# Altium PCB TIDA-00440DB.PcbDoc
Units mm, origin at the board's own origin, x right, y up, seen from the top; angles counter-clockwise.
Board outline 75 x 52 mm, 2 copper layers (Top Layer, Bottom Layer), stack 1.575 mm thick; 55 components, 30 nets, 111 pads, 12 vias.
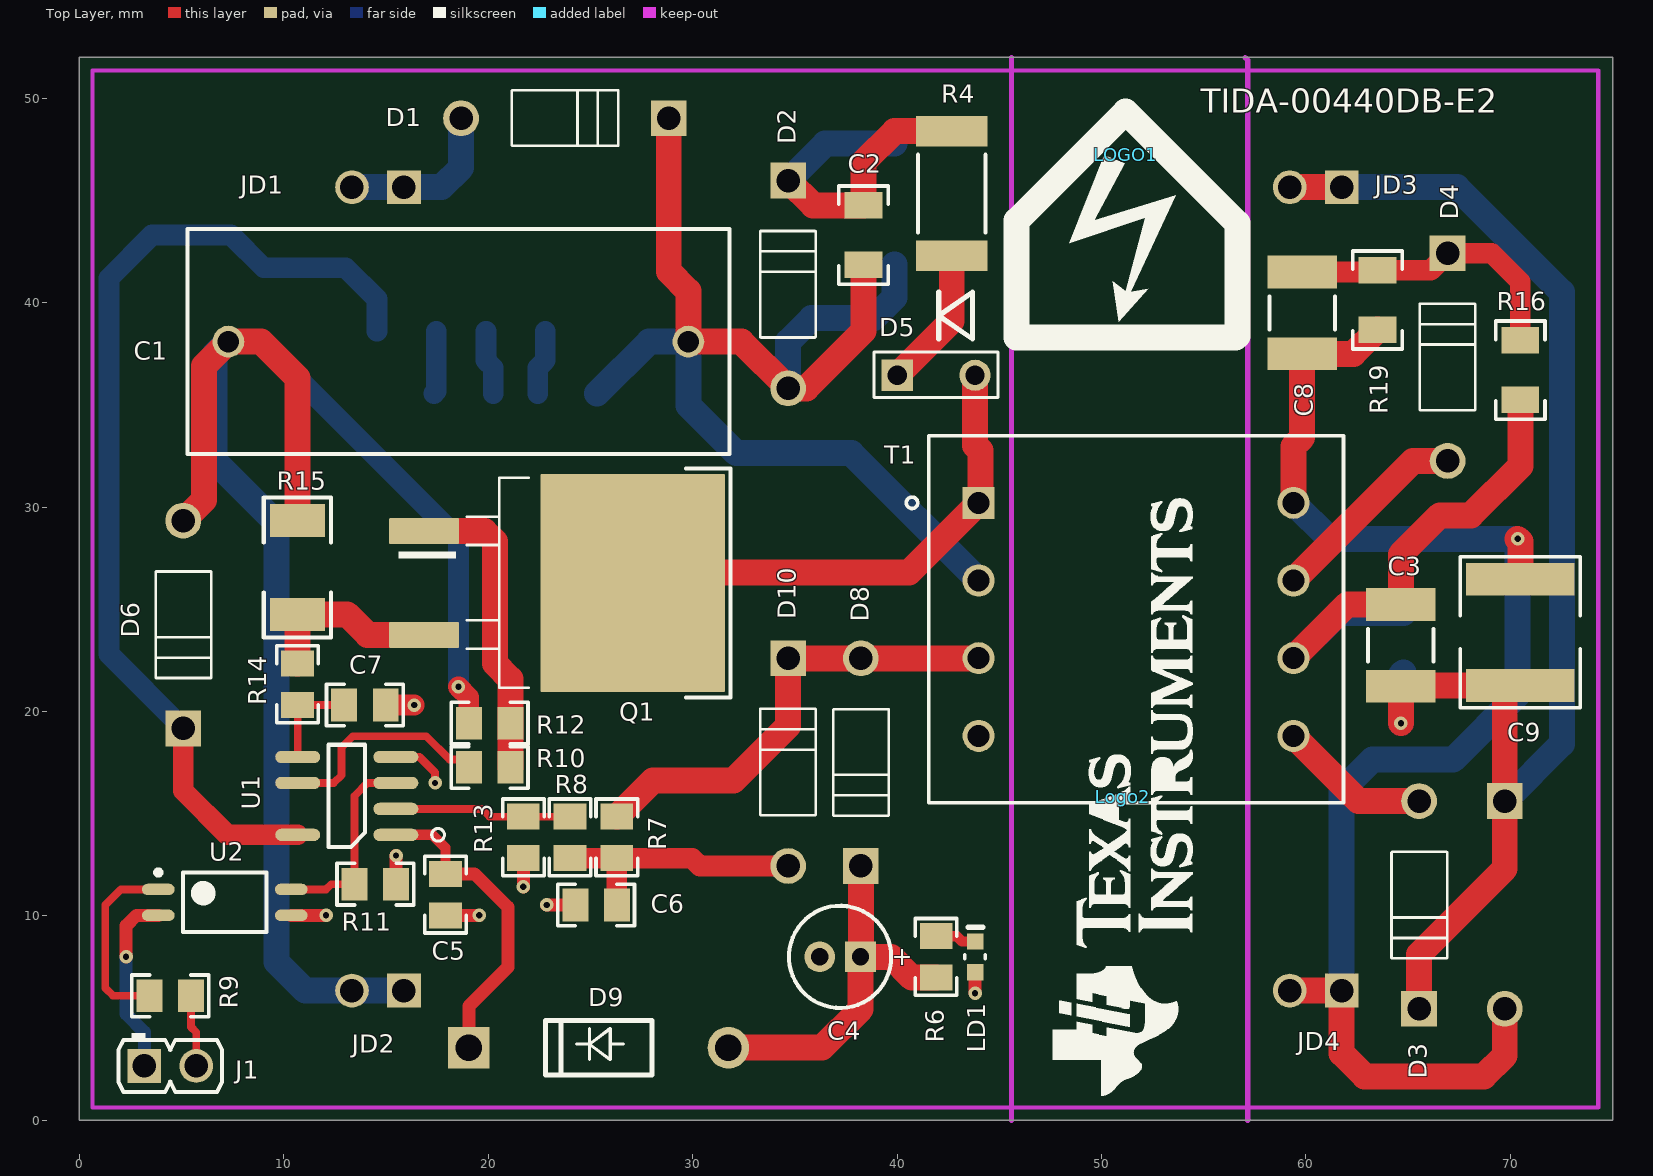
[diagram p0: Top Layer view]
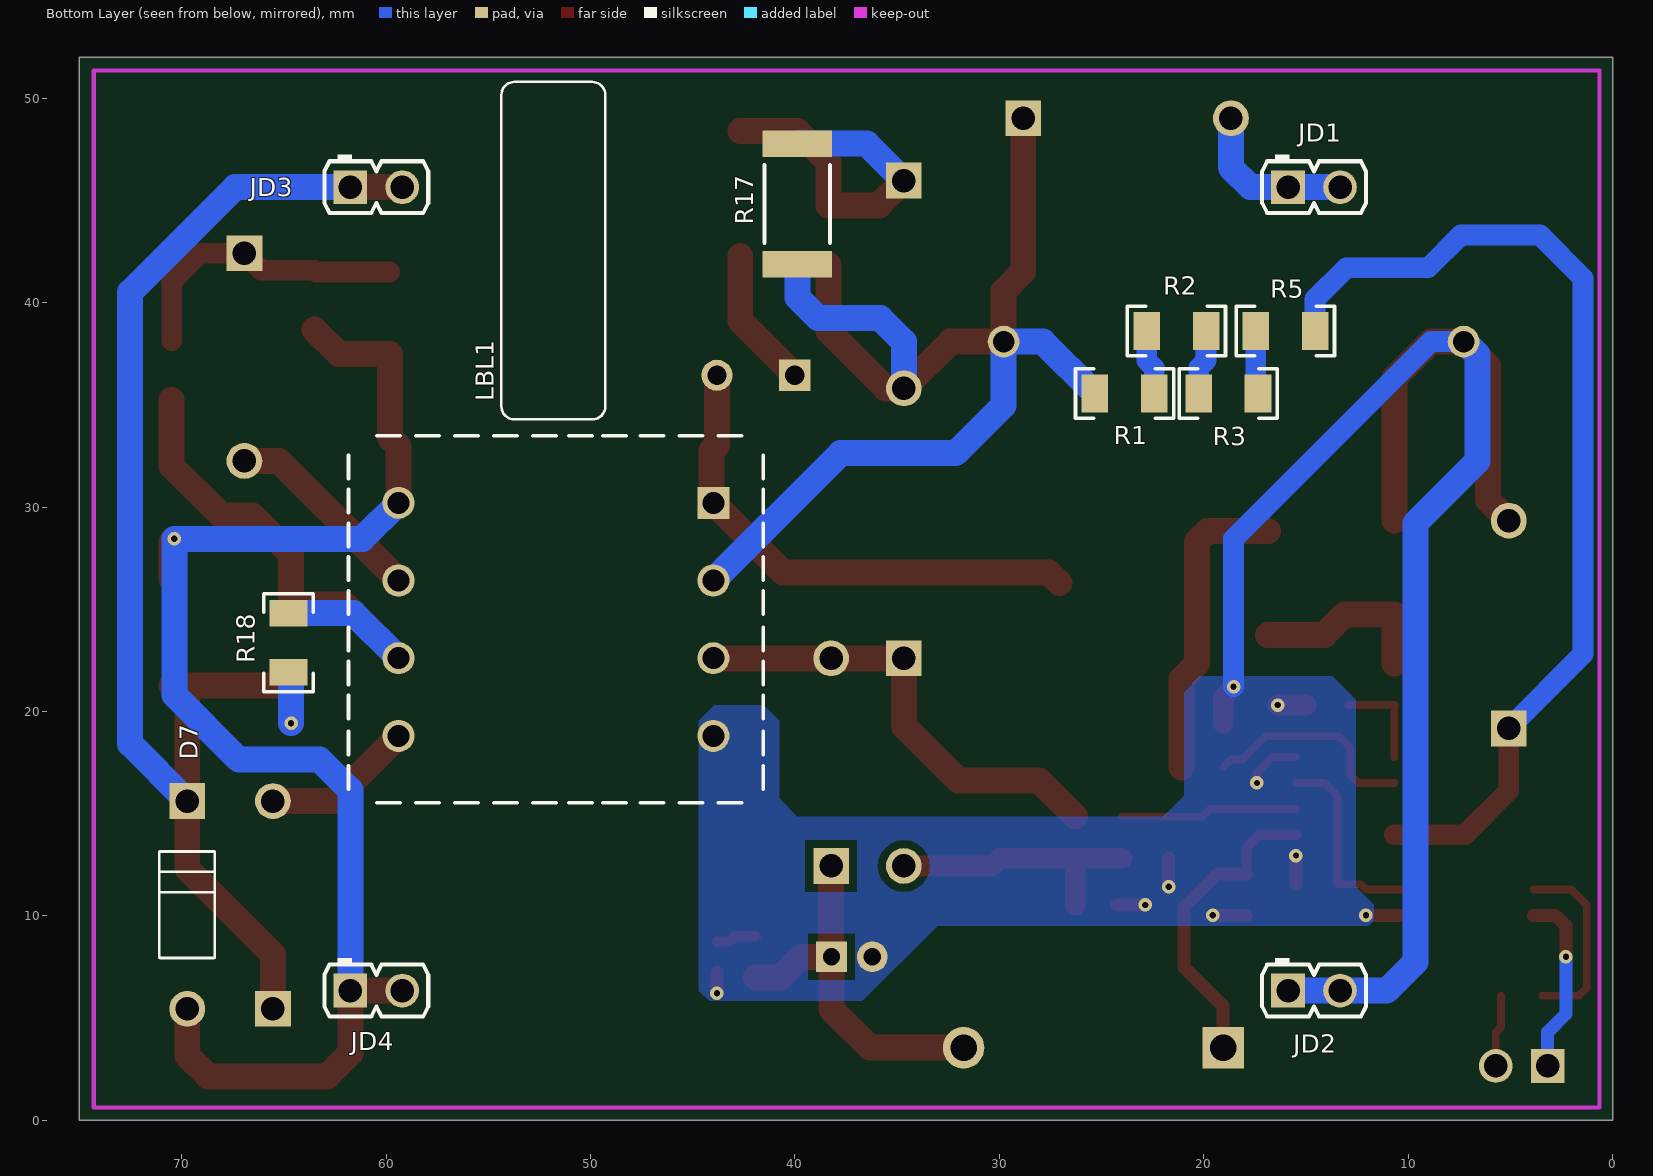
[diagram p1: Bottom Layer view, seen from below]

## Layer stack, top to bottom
Top Layer: signal copper 0.0356
Dielectric: core 1.5037, FR-4, Dk 4.8
Bottom Layer: signal copper 0.0356

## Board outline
0,0 0,52 75,52 75,0

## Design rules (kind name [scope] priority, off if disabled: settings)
AcuteAngle [All] p1: minimum=4.50000000000000E+0001 checktracksonly=FALSE
AssemblyTestPointUsage [All] p1: valid=2
Clearance "Poly_ All" [InPolygon] p1: gap=0.381
Clearance "Less Than 9 mils from PAD to PAD" [(InPadClass('Less than 9 Mil Clearance')) vs (InPadClass('All Pads'))] p2: gap=0.178
Clearance "SMT Pin Via" [IsVia vs IsSMTPin] p3: gap=0.203
Clearance "Via to Via" [IsVia vs IsVia] p4: gap=0.203
Clearance Poly_Poly [InPolygon vs InPolygon] p5: gap=0.381
Clearance [All] p6: gap=0.203
ComponentClearance ComponentClearance_Shunt [InComponentClass('Header') vs InComponentClass('Shunt')] p1: gap=0 collisioncheckmode=3 verticalgap=0 showdistances=FALSE
ComponentClearance ComponentClearance_Logo [InComponentClass('Logo')] p2: gap=1.27 collisioncheckmode=3 verticalgap=0.254 showdistances=FALSE
ComponentClearance ComponentClearance_ScrewToNut [(HasFootprint('NY PMS 440 0025 PH')) vs (HasFootprint('Keystone_1902C'))] p3: gap=0.127 collisioncheckmode=3 verticalgap=0.254 showdistances=FALSE
ComponentClearance ComponentClearance_MountingHoles [InComponentClass('Mounting Holes')] p4: gap=6.35 collisioncheckmode=3 verticalgap=2540 showdistances=FALSE
ComponentClearance ComponentClearance_SmallPassives [HasFootprint('0201*') or HasFootprint('0402*') or HasFootprint('0508') or HasFootprint('0603*') or HasFootprint('0612') or HasFootprint('0805*') or HasFootprint('0815*') or HasFootprint('0830*') or HasFootprint('1206*') or HasFootprint('1210*') or HasFootprint('1808*') or HasFootprint('1812*') or HasFootprint('1825*') or HasFootprint('2010*') or HasFootprint('2220*') or HasFootprint('2225*') or HasFootprint('2512*') or HasFootprint('2728*') or HasFootprint('3518*') vs HasFootprint('0201*') or HasFootprint('0402*') or HasFootprint('0508') or HasFootprint('0603*') or HasFootprint('0612') or HasFootprint('0805*') or HasFootprint('0815*') or HasFootprint('0830*') or HasFootprint('1206*') or HasFootprint('1210*') or HasFootprint('1808*') or HasFootprint('1812*') or HasFootprint('1825*') or HasFootprint('2010*') or HasFootprint('2220*') or HasFootprint('2225*') or HasFootprint('2512*') or HasFootprint('2728*') or HasFootprint('3518*')] p5: gap=0.508 collisioncheckmode=3 verticalgap=0.254 showdistances=FALSE
ComponentClearance ComponentClearance_THtoSMT [IsThruComponent vs IsSMTComponent] p6: gap=2.54 collisioncheckmode=3 verticalgap=0.762 showdistances=FALSE
ComponentClearance ComponentClearance_THtoTH [IsThruComponent vs IsThruComponent] p7: gap=3 collisioncheckmode=3 verticalgap=0.762 showdistances=FALSE
ComponentClearance [All] p8: gap=1.016 collisioncheckmode=3 verticalgap=0.254 showdistances=FALSE
DiffPairsRouting [All] p1: maxlimit=2.54 minlimit=0.254 mostfreqgap=0.254 maxuncoupledlength=25.4
FabricationTestPointUsage TestPointUsage [All] p1: valid=2 allowmultiple=FALSE
FabricationTestpoint Testpoint [All] p1: side=3 testpointundercomponent=TRUE minsize=1.016 maxsize=2.54 preferedsize=1.524 minholesize=0 maxholesize=1.016 preferedholesize=0.813 testpointgrid=0.025 allowsidetop=TRUE allowsidebottom=TRUE usegrid=TRUE gridtolerance=0
FanoutControl Fanout_LCC [IsLCC] p1: bgadir=Out bgaviamode=Centered fanoutstyle=Auto fanoutdirection=Alternating viagrid=0.025 // Fanout_LCC (Default Rule)
FanoutControl Fanout_BGA [IsBGA] p2: bgadir=Out bgaviamode=Centered fanoutstyle=Auto fanoutdirection=Alternating viagrid=0.025 // Fanout_BGA (Default Rule)
FanoutControl Fanout_Default [All] p4: bgadir=Out bgaviamode=Centered fanoutstyle=Auto fanoutdirection=Alternating viagrid=0.025 // Fanout_Default (Default Rule)
FanoutControl Fanout_Small [(CompPinCount < 5)] p5: bgadir=Out bgaviamode=Centered fanoutstyle=Auto fanoutdirection=OutThenIn viagrid=0.025 // Fanout_Small (Default Rule)
HoleSize [All] p1: absolutevalues=TRUE maxlimit=6.375 minlimit=0.203 maxpercent=80.000 minpercent=20.000
MinimumAnnularRing MinimumAnnularRing_ThermalPadVias [IsVia and InAnyComponent] p1: minimumring=0.15
MinimumAnnularRing [All] p2: minimumring=0.15
MinimumSolderMaskSliver MinimumSolderMaskSliver_Logo [InComponentClass('Logo') vs InComponentClass('Logo')] p1: minsoldermaskwidth=0.018
MinimumSolderMaskSliver [All] p2: minsoldermaskwidth=0.1
PlaneConnect [All] p1: planeconnectstyle=Relief reliefexpansion=0.254 reliefentries=4 reliefconductorwidth=0.254 reliefairgap=0.254
PolygonConnect [All] p1: connectstyle=Direct reliefconductorwidth=0.254 reliefentries=4 polygonreliefangle="90 Angle" airgapwidth=0.254
RoutingVias [All] p1: holewidth=0.305 width=0.66 viastyle="Through Hole" minholewidth=0.305 minwidth=0.66 maxholewidth=0.508 maxwidth=1.016
SMDToCorner [All] p1: distance=30000
SilkToSilkClearance [All] p1: silktosilkclearance=0.127
SilkscreenOverComponentPads [All] p1: minsilkscreentomaskgap=0.127
SolderMaskExpansion [All] p1: expansion=0.064
Width [All] p1: maxlimit=2.54 minlimit=0.203 preferedwidth=0.203 checkconnectedcopper=TRUE
14 further rules are at their usual default settings.

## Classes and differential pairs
component class Label: LBL1
pad class "Less than 9 Mil Clearance": U2-6 U2-7 U2-8
component class AssemblyNote: ZZ1 ZZ2 ZZ3 ZZ4
component class Pg3_Hardware_ANSI-B: !PCB LBL1 Logo2 ZZ1 ZZ2 ZZ3 ZZ4
component class Header: J1 JD1 JD2 JD3 JD4
component class Pg2: C1 C2 C3 C4 C5 C6 C7 C8 C9 D1 D2 D3 D4 D5 D6 D7 D8 D9 D10 J1 JD1 JD2 JD3 JD4 LD1 Q1 R1 R2 R3 R4 R5 R6 R7 R8 R9 R10 R11 R12 R13 R14 R15 R16 R17 R18 R19 T1 U1 U2
component class Logo: Logo2

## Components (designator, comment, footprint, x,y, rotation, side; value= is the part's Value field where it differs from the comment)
C1 "B32653A224J" B32653_2650x2050x1100 18.542,38.1 r180 top
C2 "GRM31BR73A472KW01L" 1206 38.354,43.307 r90 top
C3 "C4532X7T2W474K230KA" 1812 64.643,23.241 r90 top
C4 "UVR1V100MDD1TA" CAPPR2-5x11 37.211,8.001 r180 top
C5 "GMK212B7105KG-T" 0805_HV 17.907,11.049 r270 top
C6 "C0805C102K1RACTU" 0805_HV 25.273,10.541 r180 top
C7 "GRM2195C1H512JA01D" 0805_HV 13.97,20.32 r0 top
C8 "C4532X7T2W474K230KA" 1812 59.817,39.497 r270 top
C9 "CGA9P1X7T2J474K250KE" 2220 70.485,23.876 r90 top
D1 "1N4007" DO-41#1 23.749,49.022 r180 top
D2 "P4KE120" DO-41#1 34.671,40.894 r270 top
D3 "GP02-30-E3/73" DO-41#1 65.532,10.541 r90 top
D4 "GP02-30-E3/73" DO-41#1 66.929,37.338 r270 top
D5 "UF4007" DO-204AC_VERT 40.005,36.449 r0 top
D6 "P4KE550" DO-41#1 5.08,24.257 r90 top
D7 "P4KE550" DO-41#1 69.723,10.541 r270 bottom
D8 "1N4937-E3" DO-41#1 38.227,17.526 r90 top
D9 "D-1N4002" DO-41#2 19.05,3.556 r0 top
D10 "1N4937-E3" DO-41#1 34.671,17.526 r270 top
J1 "61300211121" WURTH_61300211121 4.445,2.667 r0 top
JD1 "61300211121" WURTH_61300211121 14.605,45.65 r180 bottom
JD2 "61300211121" WURTH_61300211121 14.605,6.35 r180 bottom
JD3 "61300211121" WURTH_61300211121 60.475,45.65 r180 bottom
JD4 "61300211121" WURTH_61300211121 60.475,6.35 r180 bottom
LBL1 "Size: 0.65\" x 0.20 \"" Label_650x200 51.816,42.545 r90 bottom
LD1 "LED_LG L29K-G2J1-24-Z" "LG L29K_GREEN" 43.815,8.001 r90 top
LOGO1 "DANGER HIGH VOLTAGE" IEC_HighVoltage_Large 51.181,47.244 r0 top
Logo2 "Texas Instruments" TI_Stacked_Overlay_Medium 51.029,15.824 r90 top
Q1 "IXTA06N120P" DDPAK 23.114,26.289 r0 top
R1 "RC1206FR-07470KL" 1206 23.876,35.56 r0 bottom
R2 "RC1206FR-07470KL" 1206 21.336,38.608 r0 bottom
R3 "RC1206FR-07470KL" 1206 18.796,35.56 r0 bottom
R4 "ERJ-1TYJ100U" 2512M 42.672,45.339 r90 top
R5 "RC1206FR-07470KL" 1206 16.002,38.608 r0 bottom
R6 "RG2012P-682-B-T5" 0805_HV 41.91,8.001 r270 top
R7 "CRCW0805100RFKEA" 0805_HV 26.289,13.843 r90 top
R8 "RG2012P-433-B-T5" 0805_HV 24.003,13.843 r270 top
R9 "CRCW0805100RFKEA" 0805_HV 4.445,6.096 r180 top
R10 "CRCW080510R0JNEA" 0805_HV 20.066,17.272 r0 top
R11 "CRCW0805100KFKEA" 0805_HV 14.478,11.557 r180 top
R12 "CRCW080510K0JNEA" 0805_HV 20.066,19.431 r0 top
R13 "CRCW080515K0FKEA" 0805_HV 21.717,13.843 r90 top
R14 "RG2012P-391-B-T5" 0805_HV 10.668,21.336 r90 top
R15 "CSRN2010FKR750" 2010 10.668,27.051 r90 top
R16 "CRCW12060000Z0EA" 1206 70.485,36.703 r270 top
R17 "CRCW25121K00FKEG" 2512 39.878,44.831 r270 bottom
R18 "CRCW12061M02FKEA" 1206 64.77,23.368 r270 bottom
R19 "CRCW12061M02FKEA" 1206 63.5,40.132 r90 top
T1 "750342792" WURTH_750342778 51.689,24.511 r0 top
U1 "UCC28711D" D0007A_N 13.081,15.875 r180 top
U2 "ACPL-217-56AE" SO4 7.112,10.668 r0 top
ZZ1 "This Assembly Note is for PCB labels only" AssemblyNoteLabel 4.318,59.817 r0 top
ZZ2 "These assemblies are ESD sensitive, ESD precautions shall be observed." AssemblyNote 4.318,65.278 r0 top
ZZ3 "These assemblies must be clean and free from flux and all contaminants. Use of no clean flux is not acceptable." AssemblyNote 4.318,63.5 r0 top
ZZ4 "These assemblies must comply with workmanship standards IPC-A-610 Class 2, unless otherwise specified." AssemblyNote 4.318,61.722 r0 top

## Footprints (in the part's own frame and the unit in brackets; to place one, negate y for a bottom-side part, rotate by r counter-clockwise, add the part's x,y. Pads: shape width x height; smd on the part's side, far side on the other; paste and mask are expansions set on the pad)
0805_HV [mil] "0805 with 30mil clearance between pads"
  rect 50x63 smd: 1(-40,0) 2(40,0)
  silkscreen extent -74,-40 74,40, body extent -43,-29 43,29, height 43
1206 [mm] "1206 from SM-752 data"
  rect 1.3x1.85 smd: 1(-1.45,0) 2(1.45,0)
  silkscreen extent -2.4,-1.21 2.4,1.21, body extent -1.7,-0.9 1.7,0.9, height 1.35
1812 [mm]
  rect 1.6x3.4 smd: 1(-2,0) 2(2,0)
  silkscreen extent -0.8,-1.6 0.8,1.6, body extent -2.4,-1.7 2.4,1.7, height 1.35
2010 [mm] "Chip Capacitor, Body 5.08x2.54mm, IPC Medium Density"
  rect 1.6x2.7 smd: 1(-2.3,0) 2(2.3,0)
  silkscreen extent -3.42,-1.65 3.42,1.65, body extent -2.73,-1.45 2.73,1.45, height 1.66
2220 [mm] "Chip Capacitor, Body 5.7x5.0mm, IPC Medium Density"
  rect 1.6x5.3 smd: 1(-2.6,0) 2(2.6,0)
  silkscreen extent -3.69,-2.94 3.69,2.94, body extent -2.95,-2.62 2.95,2.62, height 1.35
2512 [mm] "Chip Resistor, Body 6.3x3.2mm, IPC Medium Density"
  rect 1.3x3.4 smd: 1(-2.95,0) 2(2.95,0)
  silkscreen extent -1.9,-1.6 1.9,1.6, body extent -3.22,-1.67 3.22,1.67, height 0.71
2512M [mm] "Chip Resistor, Body 6.3x3.2mm, IPC Low Density"
  rect 1.5x3.5 smd: 1(-3.05,0) 2(3.05,0)
  silkscreen extent -1.9,-1.65 1.9,1.65, body extent -3.22,-1.67 3.22,1.67, height 0.71
AssemblyNote [mm] "Assembly Note"
AssemblyNoteLabel [mm] "Assembly Note for PCB Labels"
B32653_2650x2050x1100 [mm] "TH, 2-Leads, Body 26.5x11mm, Pin Spacing 22.5mm"
  round 1.55 hole 1.05: 1(-11.25,0) 2(11.25,0)
  silkscreen extent -13.25,-5.5 13.25,5.5, body extent -13.25,-5.5 13.25,5.5, height 20.5
CAPPR2-5x11 [mm] "Capacitor, Electrolytic, Radial; Body 5 x 11 mm (Dia.xH typ); Pin Spacing 2 mm (typ)"
  rect 1.5x1.5 hole 0.85: 1(-1,0)
  round 1.5 hole 0.85: 2(1,0)
  silkscreen extent -2.5,-2.5 2.5,2.5, body extent -2.53,-2.53 2.53,2.52, height 11.29
D0007A_N [mm] "SOIC, 7-Leads, Body 4.9x3.9mm, Pitch 1.27mm, IPC Medium Density"
  oval 2.2x0.6 smd: 1(-2.4,1.905) 2(-2.4,0.635) 3(-2.4,-0.635) 4(-2.4,-1.905) 5(2.4,-1.905) 6(2.4,-0.635) 8(2.4,1.905)
  silkscreen extent -0.9,-2.5 0.9,2.5, body extent -3,-2.5 3,2.5, height 1.54
DDPAK [mil] "D2-PAK, 3-Pads, Body 9.7x10.4mm (max), TO-263AB, using Vishay Silionix recommended pad sizes"
  rrect8% 135x49.49 smd: 1(-246.06,100) 3(-246.06,-100)
  rrect1% 355x420 smd paste-181.1: 4(155.51,0)
  silkscreen extent -295,-220 344,220, body extent -295,-202 324,202, height 180
DO-41#1 [mm] "diode"
  rect 1.75x1.75 hole 1.15: 1(-5.08,0)
  round 1.75 hole 1.15: 2(5.08,0)
  silkscreen extent -2.62,-1.37 2.59,1.35, body extent -5.51,-1.36 5.51,1.36, height 2.72
DO-41#2 [mm]
  rect 2.032x2.032 hole 1.295: 1(0,0)
  round 2.032 hole 1.295: 2(12.7,0)
  silkscreen extent 3.75,-1.33 8.95,1.33
DO-204AC_VERT [mil]
  rect 60x60 hole 37: 1(0,0)
  round 60 hole 37: 2(150,0)
  silkscreen extent 80,70 145,160
IEC_HighVoltage_Large [mm]
  silkscreen extent -5.33,-8.94 5.46,2.11
Label_650x200 [mil] "Thermal Transfer Label"
  round 1 on Mech14: 0(0,0)
  silkscreen extent -325,-100 325,100, body extent -326,-101 326,101, height 1
"LG L29K_GREEN" [mm] "OSRAM"
  rect 0.8x0.8 smd paste-0.4: 1(-0.75,0) 2(0.75,0)
  silkscreen extent -0.1,-0.5 1.45,0.5, body extent -0.9,-0.45 0.9,0.45, height 0.67
SO4 [mm] "SOP, 4-Leads, Body 2.65x4.60mm, Pitch 1.27mm, IPC Medium Density"
  oval 1.6x0.55 smd: 1(-3.25,0.635) 2(-3.25,-0.635) 3(3.25,-0.635) 4(3.25,0.635)
  silkscreen extent -3.37,-1.45 2.05,1.58, body extent -2.4,-1.45 2.4,1.45, height 2.2
TI_Stacked_Overlay_Medium [mm]
  silkscreen extent -14.62,-3.44 14.62,3.42
WURTH_750342778 [mm] "TRANSFORMER, 3.5mH, 10%, THRU"
  rect 1.57x1.57 / inner round 1.57 / far side rect 1.57x1.57 hole 1.07: 1(-7.7,5.7)
  round 1.57 hole 1.07: 2(-7.7,1.9) 3(-7.7,-1.9) 4(-7.7,-5.7) 5(7.7,-5.7) 6(7.7,-1.9) 7(7.7,1.9) 8(7.7,5.7)
  silkscreen extent -11.24,-8.98 10.15,8.98, body extent -10.15,-8.98 10.15,8.98, height 14.3
WURTH_61300211121 [mm] "Header, 2.54mm, 2x1, TH"
  rect 1.65x1.65 hole 1.15: 1(-1.27,0)
  round 1.65 hole 1.15: 2(1.27,0)
  silkscreen extent -2.54,-1.27 2.54,1.6, body extent -2.54,-1.27 2.54,1.27, height 8.54

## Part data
C1: "CAP, Film, 0.22 µF, 1000 V, +/- 5%, TH"
C2: "CAP, CERM, 4700pF, 1000V, +/-10%, X7R, 1206"
C3 C8: library part GRM43DR72E474KW01L, "CAP, CERM, 0.47 µF, 450 V, +/- 10%, X7T, 1812"
C4: "CAP, AL, 10uF, 35V, +/-20%, TH"
C5: "CAP, CERM, 1uF, 35V, +/-10%, X7R, 0805"
C6: "CAP, CERM, 1000pF, 100V, +/-10%, X7R, 0805"
C7: "CAP, CERM, 5100 pF, 50 V, +/- 5%, C0G/NP0, 0805"
C9: library part GRM55DR73A104KW01L, "CAP, CERM, 0.47 µF, 630 V, +/- 10%, X7T, 2220"
D1: "Diode, P-N, 1000V, 1A, TH"
D2: library part P4KE550, "TVS DIODE"
D3 D4: library part 1N4007, "Diode, P-N, 3000V, 0.25A, TH"
D5: "DIODE FAST REC 1KV 1A DO41"
D6 D7: "TVS DIODE 495VWM 798VC AXIAL"
D8 D10: "Diode, Switching, 600V, 1A, TH"
D9: "Diode, Signal, 100V, 1A"
J1 JD1 JD2 JD3 JD4: "Header, 2.54 mm, 2x1, Gold, TH"
LBL1: library part THT-14-423-10, "Thermal Transfer Printable Labels, 0.650\" W x 0.200\" H - 10,000 per roll"
LD1: "LED SmartLED Green 570NM"
LOGO1: library part IEC_HighVoltage, "IEC 61010-1 High Voltage Warning"
Logo2: library part TI_Logo, "Texas Instrument Corporate Signature"
Q1: "MOSFET, N-CH, 1200 V, 0.6 A, DDPAK"
R1 R2 R3 R5: "RES, 470k ohm, 1%, 0.25W, 1206"
R4: "RES, 10 ohm, 5%, 1W, 2512"
R6: "RES, 6.80k ohm, 0.1%, 0.125W, 0805"
R7 R9: "RES, 100, 1%, 0.125 W, 0805"
R8: "RES, 43.0 k, 0.1%, 0.125 W, 0805"
R10: "RES, 10, 5%, 0.125 W, 0805"
R11: "RES, 100 k, 1%, 0.125 W, 0805"
R12: "RES, 10 k, 5%, 0.125 W, 0805"
R13: "RES, 15.0 k, 1%, 0.125 W, 0805"
R14: "RES, 390, 0.1%, 0.125 W, 0805"
R15: "RES, 0.75, 1%, 1 W, 2010"
R16: "RES, 0, 5%, 0.25 W, 1206"
R17: "RES, 1.00 k, 1%, 1 W, 2512"
R18 R19: "RES, 1.02 M, 1%, 0.25 W, 1206"
T1: "Transformer, 738uH, SMT"
U1: "IC REG CTRLR FLYBK ISO 7SOIC"
U2: "Optocoupler, DC Input ,Half-Pitch Phototransistor, 3000 VRMS, SO-4"
ZZ1: library part AssemblyNoteLabel
ZZ2 ZZ3 ZZ4: library part AssemblyNote

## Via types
v1: diameter 0.66, hole 0.305, Top Layer to Bottom Layer, 12 vias

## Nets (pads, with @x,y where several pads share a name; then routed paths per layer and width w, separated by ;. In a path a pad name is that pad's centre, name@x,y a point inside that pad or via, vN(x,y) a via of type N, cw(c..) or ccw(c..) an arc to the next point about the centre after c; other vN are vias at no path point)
DC+: D1.2 JD1.1 JD1.2 | length 8.1
  Bottom Layer w1.27: JD1.2 JD1.1 17.71,45.65 18.669,46.609 D1.2
GND: J1.1 U2.2 | length 9
  Top Layer w0.635: v1(2.286,8.001) 2.286,9.525 2.794,10.033 U2.2
  Bottom Layer w0.635: v1(2.286,8.001) 2.286,5.207 3.175,4.318 J1.1
GND_ISO: C8.2 C9.2 D7.2 JD4.1 JD4.2 R19.1 T1.8 | length 70.1
  Top Layer w1.27: JD4.2 JD4.1 61.745,3.279 62.865,2.159 68.707,2.159 69.723,3.175 D7.2 ; T1.8 59.389,32.973 59.817,33.401 C8.2 62.315,37.497 R19.1 ; v1(70.358,28.448) 70.485,28.321 C9.2
  Bottom Layer w1.27: T1.8 61.152,28.448 v1(70.358,28.448) 70.358,20.818 67.193,17.653 63.246,17.653 61.745,16.152 JD4.1
HV_START: D6.1 R5.1 U1.8 | length 49.9
  Top Layer w1.016: D6.1 5.08,16.129 7.239,13.97 U1.8
  Bottom Layer w1.016: D6.1 1.448,22.809 1.448,41.199 3.556,43.307 7.423,43.307 9.017,41.713 13.024,41.713 14.552,40.185 R5.1
NetC1_1: C1.1 C2.1 D1.1 D2.2 R1.2 R17.2 T1.2 | length 61.6
  Top Layer w1.27: D1.1 28.829,41.529 29.792,40.566 C1.1 32.385,38.1 D2.2 35.56,35.814 38.354,38.608 C2.1
  Bottom Layer w1.27: R1.2 27.866,38.1 C1.1 29.792,34.978 32.131,32.639 37.761,32.639 T1.2 ; D2.2 34.671,38.1 35.814,39.243 38.862,39.243 39.878,40.259 R17.2
NetC2_2: C2.2 D2.1 R4.2 R17.1 | length 17.2
  Top Layer w1.27: D2.1 35.888,44.757 C2.2 38.354,46.863 39.88,48.389 R4.2
  Bottom Layer w1.27: D2.1 36.478,47.781 R17.1
NetC3_1: C3.1 C9.1 D3.1 D7.1 JD3.1 JD3.2 R18.2 | length 69.5
  Top Layer w1.27: JD3.2 JD3.1 ; v1(64.643,19.431) C3.1 64.678,21.276 C9.1@70.171,21.276 ; D3.1 65.532,8.128 69.723,12.319 D7.1 69.723,20.828 C9.1@70.171,21.276 ; C9.1@70.231,21.336 C9.1@70.171,21.276 ; C9.1 C9.1@70.171,21.276
  Bottom Layer w1.27: JD3.1 67.38,45.65 72.517,40.513 72.517,18.415 D7.1 ; v1(64.643,19.431) 64.643,21.791 R18.2
NetC3_2: C3.2 R16.2 R18.1 T1.6 | length 26
  Top Layer w1.27: T1.6 62.019,25.241 C3.2 64.643,27.686 66.548,29.591 68.072,29.591 70.485,32.004 R16.2
  Bottom Layer w1.27: T1.6 61.596,24.818 R18.1
NetC4_1: C4.1 D8.1 D9.2 R6.2 | length 18.4
  Top Layer w1.27: D9.2 36.322,3.556 38.211,5.445 C4.1 ; D8.1 38.227,8.017 C4.1 ; R6.2 40.727,6.985 39.711,8.001 C4.1
NetC6_1: C6.1 D10.2 R7.1 R8.2 | length 13.1
  Top Layer w1.016: R8.2 R7.1 ; C6.1 R7.1 ; D10.2 30.353,12.446 29.972,12.827 R7.1
NetC7_1: C7.1 R14.1 U1.5 | length 4.8
  Top Layer w0.381: U1.5 10.681,20.307 R14.1 C7.1
NetC8_1: C8.1 D4.1 R16.1 R19.2 | length 14.5
  Top Layer w1.016: C8.1 63.415,41.497 R19.2 66.093,41.582 D4.1 69.088,42.418 70.485,41.021 R16.1
NetD3_2: D3.2 T1.5 | length 7.5
  Top Layer w1.27: T1.5 62.579,15.621 D3.2
NetD4_2: D4.2 T1.7 | length 10
  Top Layer w1.27: T1.7 65.236,32.258 D4.2
NetD5_1: D5.1 R4.1 | length 6.9
  Top Layer w1.27: D5.1 42.672,39.116 R4.1
NetD5_2: D5.2 Q1.4 T1.1 | length 24.9
  Top Layer w1.27: Q1.4 27.572,26.797 40.575,26.797 T1.1 44.069,30.291 44.069,32.766 43.815,33.02 D5.2
NetJ1_2: J1.2 R9.1 | length 3.5
  Top Layer w0.381: R9.1 5.461,4.572 5.715,4.318 J1.2
NetLD1_2: LD1.2 R6.1 | length 2
  Top Layer w0.508: R6.1 42.926,9.017 43.192,8.751 LD1.2
NetQ1_1: Q1.1 R10.2 R12.2 | length 15
  Top Layer w1.27: Q1.1 19.812,28.829 20.32,28.321 20.32,22.352 21.082,21.59 R12.2 R10.2
NetQ1_3: Q1.3 R14.2 R15.1 | length 9
  Top Layer w1.27: R14.2 R15.1 13.095,24.751 14.097,23.749 Q1.3
NetR1_1: R1.1 R2.2 | length 3.2
  Bottom Layer w1.016: R1.1 22.426,36.82 22.786,37.18 R2.2
NetR2_1: R2.1 R3.2 | length 3.2
  Bottom Layer w1.016: R2.1 19.886,37.18 20.246,36.82 R3.2
NetR3_1: R3.1 R5.2 | length 3.1
  Bottom Layer w1.016: R3.1 17.452,35.666 R5.2
NetR8_1: R8.1 R13.2 U1.2 | length 8.9
  Top Layer w0.381: U1.2 19.685,15.24 20.066,14.859 R13.2 ; R13.2@21.463,14.859 R13.2 ; R8.1 R13.2
NetR9_2: R9.2 U2.1 | length 9.3
  Top Layer w0.381: R9.2 1.651,6.096 1.27,6.477 1.27,10.541 2.032,11.303 U2.1
NetR10_1: R10.1 U1.6 | length 10.7
  Top Layer w0.381: U1.6 12.446,16.51 12.827,16.891 12.827,18.248 13.375,18.796 16.967,18.796 18.11,17.653 18.669,17.653 R10.1
NTC: R11.2 U1.3 U2.4 | length 9.8
  Top Layer w0.381: U2.4 12.065,11.303 12.319,11.557 R11.2 13.462,15.875 14.097,16.51 U1.3
PGND: C1.2 C4.2 C5.2 C6.2 C7.2 D6.2 JD2.1 JD2.2 LD1.1 R11.1 R12.1 R13.1 R15.2 T1.4 U1.4 U2.3 | length 96.7
  Top Layer w0.381: U1.4 16.637,17.78 17.399,17.018 v1(17.399,16.51)
  Top Layer w0.635: U2.3 v1(12.065,10.033) ; R11.1 v1(15.494,12.954) ; C5.2 v1(19.558,10.033) ; v1(21.717,11.43) R13.1 ; v1(22.86,10.541) C6.2 ; v1(43.815,6.223) LD1.1
  Top Layer w1.016: C7.2 v1(16.383,20.32) ; v1(18.542,21.209) 19.05,20.701 R12.1
  Top Layer w1.27: D6.2 6.096,30.353 6.096,36.904 C1.2 8.89,38.1 10.668,36.322 R15.2
  Bottom Layer w1.016: C1.2 8.89,38.1 18.542,28.448 v1(18.542,21.209)
  Bottom Layer w1.27: C1.2 7.239,38.1 6.604,37.465 6.604,32.258 9.652,29.21 9.652,7.747 11.049,6.35 JD2.2 JD2.1
VDD: C5.1 D9.1 U1.1 | length 15.4
  Top Layer w0.508: U1.1 17.272,13.97 17.907,13.335 C5.1
  Top Layer w0.635: C5.1 19.329,12.065 20.955,10.439 20.955,7.493 19.05,5.588 D9.1
VFB: D8.2 D10.1 R7.2 T1.3 | length 22.8
  Top Layer w1.27: R7.2 28.067,16.637 32.004,16.637 34.671,19.304 D10.1 D8.2 43.984,22.606 T1.3
pads on no net: LBL1.0

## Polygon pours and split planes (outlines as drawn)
PGND on Bottom Layer "Multi-Layer-No Net" (solid, remove dead copper, pour order 2): 43.942,20.32 44.704,19.558 44.704,6.35 44.196,5.842 36.703,5.842 33.02,9.525 11.938,9.525 11.684,9.779 11.684,10.541 12.573,11.43 12.573,20.574 13.716,21.717 20.193,21.717 20.955,20.955 20.955,15.875 21.971,14.859 39.878,14.859 40.767,15.748 40.767,19.558 41.529,20.32

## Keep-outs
Top Layer:
  lines w0.254: 45.593,0 45.593,52 ; 57.023,52 57.15,51.873 57.15,0
Keep-Out Layer:
  lines w0.203: 0.635,0.635 74.295,0.635 74.295,51.365 0.635,51.365 0.635,0.635
  text ".Layer_Name" at 5.893,-28.283 h1.52

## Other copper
Top Layer:
  text ".Layer_Name" at 5.893,-28.283 h1.52
Bottom Layer:
  text ".Layer_Name" at 5.893,-28.283 h1.52

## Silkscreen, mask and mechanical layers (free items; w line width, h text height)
Top Overlay:
  circle w0.152: c17.546,13.97 r0.31
  lines w0.152: 38.862,35.357 38.862,37.592 44.933,37.592 44.933,35.357 38.862,35.357
  text "TIDA-00440DB-E2" at 54.864,48.895 h2.03
  text "JD1" at 7.874,45.339 h0.89
  text "JD3" at 63.373,45.339 h0.89
  text "JD4" at 59.563,3.429 h0.89
  text "JD2" at 13.335,3.302 h0.89
  text ".Layer_Name" at 5.893,-28.283 h1.52
Bottom Overlay:
  text ".Layer_Name" at 7.188,-28.118 h1.52
Top Paste:
  text ".Layer_Name" at 5.893,-28.283 h1.52
Bottom Paste:
  text ".Layer_Name" at 5.893,-28.283 h1.52
Top Solder:
  text ".Layer_Name" at 5.893,-28.283 h1.52
  text ".Layer_Name" at 5.893,-28.283 h1.52
Bottom Solder:
  text ".Layer_Name" at 5.893,-28.283 h1.52
Drill Guide:
  text ".Layer_Name" at 5.893,-28.283 h1.52
M1 Board Outline:
  the board outline again, w0.254
M2 Board Dimensions:
  rectangle: -8.776,-13.729 -5.601,-10.554
  rectangle: -5.601,-16.904 3.924,-13.729
  lines w0.178: -8.776,-13.729 16.624,-13.729 ; -5.601,-16.904 -5.601,-10.554 ; -2.426,-16.904 -2.426,-10.554 ; 3.924,-16.904 3.924,-10.554 ; 10.274,-16.904 10.274,-10.554 ; -8.776,-16.904 16.624,-16.904 16.624,-10.554 -8.776,-10.554 -8.776,-16.904
  lines w0.254: -8.776,-18.555 -8.776,-18.047 ; -7.252,-18.809 -8.776,-18.301 ; -7.252,-17.793 -8.776,-18.301 ; -2.576,-18.301 -8.776,-18.301 ; 10.425,-18.301 16.624,-18.301 ; 15.1,-18.809 16.624,-18.301 ; 15.1,-17.793 16.624,-18.301 ; 16.624,-18.555 16.624,-18.047
  text "25.4 (mm)" at -2.322,-19.215 h1.52
M3 3D STEP Top:
  text ".Layer_Name" at 5.893,-28.283 h1.52
M4 3D STEP Bottom:
  text ".Layer_Name" at 5.893,-28.283 h1.52
M5 Assembly Top:
  circle w0.152: c14.249,13.995 r0.27
  lines w0.254: -16.18,-30.103 151.46,-30.103 ; -16.18,-24.939 151.511,-24.939 ; -16.18,-19.774 -16.18,-35.268 85.547,-35.268 151.511,-35.268 151.511,-19.774 -16.167,-19.774 -16.167,-35.268 23.851,-35.268 ; 46.431,-35.268 46.431,-19.774 ; 78.613,-24.939 78.613,-19.774 ; 99.949,-24.939 99.949,-19.774 ; 115.748,-35.433 115.748,-30.281
  text "COMPONENTS MARKED 'DNP' SHOULD NOT BE POPULATED." at 20.536,-14.567 h0.89
  text "ASSEMBLY VARIANT:" at 20.523,-17.501 h0.89
  text ".VariantName" at 46.838,-17.501 h0.89
  text "PCB VIEWED FROM TOP SIDE" at -14.567,-23.131 h0.89
  text "BOARD #:" at 48.336,-23.131 h0.89
  text "TIDA-00440DB" at 60.02,-23.139 h1.52
  text "REV:" at 83.642,-23.131 h0.89
  text ".PCB_Rev" at 91.046,-23.131 h0.89
  text "SVN REV:" at 104.927,-23.131 h0.89
  text ".VersionControl_RevNumber" at 117.78,-23.131 h0.89
  text "IGNORE ->" at -14.567,-28.283 h0.89
  text "ASSEMBLY TOP" at 6.223,-28.423 h1.52
  text "PLOT NAME =" at -14.567,-33.511 h0.89
  text ".plot_File_Name" at 5.893,-33.511 h0.89
  text "GENERATED    :" at 48.387,-33.511 h0.89
  text ".Print_Date" at 70.472,-33.511 h0.89
  text ".Print_Time" at 88.989,-33.511 h0.89
  text "TEXAS INSTRUMENTS" at 121.107,-33.511 h0.89
M6 Assembly Bottom:
  lines w0.254: -16.192,-24.951 151.498,-24.951 ; -16.142,-30.116 151.498,-30.116 ; 19.571,-35.446 19.571,-30.294 ; 35.369,-24.951 35.369,-19.787 ; 56.706,-24.951 56.706,-19.787 ; 88.887,-35.281 88.887,-19.787 ; 111.468,-35.281 151.486,-35.281 151.486,-19.787 -16.192,-19.787 -16.192,-35.281 49.771,-35.281 151.498,-35.281 151.498,-19.787
  text "COMPONENTS MARKED 'DNP' SHOULD NOT BE POPULATED." at 146.228,-14.554 h0.89
  text ".VariantName" at 119.71,-17.501 h0.89
  text "ASSEMBLY VARIANT:" at 146.101,-17.501 h0.89
  text ".VersionControl_RevNumber" at 17.539,-23.144 h0.89
  text "SVN REV:" at 30.391,-23.144 h0.89
  text ".PCB_Rev" at 44.272,-23.144 h0.89
  text "REV:" at 51.676,-23.144 h0.89
  text "BOARD #:" at 86.982,-23.144 h0.89
  text "PCB VIEWED FROM BOTTOM SIDE" at 149.885,-23.144 h0.89
  text "TIDA-00440DB" at 77.826,-23.165 h1.52
  text "IGNORE ->" at 55.952,-28.283 h0.89
  text "ASSEMBLY BOTTOM" at 28.346,-28.423 h1.52
  text "TEXAS INSTRUMENTS" at 14.211,-33.524 h0.89
  text ".Print_Time" at 46.33,-33.524 h0.89
  text ".Print_Date" at 64.846,-33.524 h0.89
  text "GENERATED    :" at 86.931,-33.524 h0.89
  text ".plot_File_Name" at 129.426,-33.524 h0.89
  text "PLOT NAME =" at 149.885,-33.524 h0.89
M9 Title Sheet:
  drawing of 57 lines, arcs and shapes, not listed
  text "1" at 10.029,197.65 h1.78
  text "2" at 73.419,197.65 h1.78
  text "3" at 136.648,197.65 h1.78
  text "4" at 200.317,197.65 h1.78
  text "5" at 263.792,197.65 h1.78
  text "6" at 327.419,197.65 h1.78
  text "A" at -19.342,168.618 h1.78
  text "A" at 356.578,168.618 h1.78
  text "B" at -19.342,108.166 h1.78
  text "B" at 356.578,108.166 h1.78
  text "C" at -19.342,47.841 h1.78
  text "C" at 356.578,47.841 h1.78
  text "PROJECT TITLE:" at 279.362,0.572 h1.14
  text ".PRJ_Title" at 280.632,-2.815 h1.78
  text "DESIGNED FOR:" at 279.362,-7.074 h1.14
  text ".PRJ_Customer" at 280.632,-10.63 h1.78
  text "D" at -19.342,-12.357 h1.78
  text "D" at 356.578,-12.357 h1.78
  text "FILE NAME:" at 279.362,-14.694 h1.14
  text ".PCB_File_Name_No_Path" at 280.632,-17.742 h1.78
  text "Texas Instruments (TI) and/or its licensors do not warrant the accuracy or completeness of this specification" at 153.137,-21.853 h1.14
  text "ENGINEER:" at 279.362,-22.06 h1.14
  text "LAYOUT BY:" at 317.589,-22.06 h1.14
  text "or any information contained therein. TI and/or its licensors do not warrant that this design will meet" at 151.994,-24.714 h1.14
  text ".PRJ_Engineer" at 280.632,-25.997 h1.78
  text "Manjunath M" at 318.872,-25.997 h1.78
  text "the specifications, will be suitable for your application or fit for any particular purpose, or will operate in" at 151.994,-27.576 h1.14
  text "ALTIUM DESIGNER VERSION:" at 317.589,-29.934 h1.14
  text "an implementation. TI and/or its licensors do not warrant that the design is production worthy. You should" at 151.994,-30.438 h1.14
  text "completely validate and test your design implementation to confirm the system functionality for your application." at 153.137,-33.299 h1.14
  text ".print_Scale" at 280.632,-33.32 h1.78
  text ".Application_BuildNumber" at 318.872,-33.32 h1.78
  text "1" at 10.029,-38.57 h1.78
  text "2" at 73.419,-38.57 h1.78
  text "3" at 136.648,-38.57 h1.78
  text "4" at 200.317,-38.57 h1.78
  text "5" at 263.792,-38.57 h1.78
  text "6" at 327.419,-38.57 h1.78
M10 Fab Notes:
  drawing of 228 lines, arcs and shapes, not listed
  text "DESIGN INFORMATION" at 305.715,166.497 h1.52
  text "(REFER ALSO ARRAY/PANEL PROFILING INFORMATION)" at 296.531,162.389 h1.52
  text "BOARD SIZE" at 279.107,162.281 h1.52
  text "75mm" at 290.85,159.034 h1.52
  text "X" at 303.694,159.034 h1.52
  text "52mm" at 309.57,159.034 h1.52
  text "Number of Layers :" at 289.343,154.026 h1.52
  text "2" at 317.151,153.772 h1.52
  text "MIN. TRACK WIDTH:" at 289.343,150.495 h1.52
  text "15" at 316.484,150.495 h1.52
  text "MIL" at 321.118,150.495 h1.52
  text "15" at 316.611,147.193 h1.52
  text "MIN. CLEARANCE:" at 289.343,147.142 h1.52
  text "MIL" at 321.118,147.142 h1.52
  text "MIN. VIA PAD SIZE:" at 289.343,143.789 h1.52
  text "26" at 316.426,143.789 h1.52
  text "MIL" at 321.118,143.789 h1.52
  text "0.1778mm (7MIL)" at 306.996,140.19 h1.52
  text "MINIMUM ANNULAR RING" at 280.981,140.081 h1.52
  text "EXTERNAL" at 326.644,140.081 h1.52
  text "PER" at 286.061,137.084 h1.52
  text "IPC-D-275 CLASS 2 LEVEL C" at 291.649,137.084 h1.52
  text "MIL, HOLES" at 329.45,134.232 h1.52
  text "+/-" at 319.481,134.214 h1.52
  text "+/-" at 341.173,134.214 h1.52
  text "REGISTRATION TOLERANCES:" at 280.981,134.087 h1.52
  text "METAL" at 311.455,134.087 h1.52
  text "5" at 326.09,134.087 h1.52
  text "3" at 347.249,134.087 h1.52
  text "MIL" at 350.201,134.087 h1.52
  text "MATERIAL:" at 279.081,128.766 h1.52
  text "FR-4 High Tg" at 304.137,125.202 h1.52
  text "X" at 286.041,124.984 h1.52
  text "FR-408" at 289.775,124.984 h1.52
  text "OTHER" at 327.57,124.984 h1.52
  text "63 MIL (1.6mm) +/-10%" at 297.905,120.851 h1.52
  text "THICKNESS:" at 280.981,120.742 h1.52
  text "X" at 294.65,120.742 h1.52
  text "OTHER" at 330.542,120.742 h1.52
  text "TOLERANCE:" at 280.981,116.729 h1.52
  text "X" at 302.299,116.729 h1.52
  text "ANSI IPC-6012 TYPE 3 CLASS 2" at 307.047,116.729 h1.52
  text "OTHER +/-" at 307.047,112.767 h1.52
  text "BOW & TWIST:" at 280.981,108.779 h1.52
  text "X" at 302.299,108.779 h1.52
  text "ANSI IPC-6012 TYPE 3 CLASS 2" at 307.047,108.779 h1.52
  text "OTHER +/-" at 307.047,104.753 h1.52
  text "COPPER THICKNESS (FINISHED):" at 279.081,101.311 h1.52
  text "1.4MIL (1oz)" at 301.433,97.432 h1.52
  text "2MIL (1.4oz)" at 320.915,97.432 h1.52
  text "2.8MIL (2oz)" at 339.381,97.432 h1.52
  text "OUTER:" at 288.149,97.324 h1.52
  text "X" at 298.171,97.307 h1.52
  text "1.4MIL (1oz)" at 301.433,93.445 h1.52
  text "2.8MIL (2oz)" at 320.915,93.445 h1.52
  text "N/A" at 339.369,93.454 h1.52
  text "INNER SIGNAL:" at 280.807,93.336 h1.52
  text "DRILLING:" at 279.081,89.805 h1.52
  text "REFERENCE:" at 280.981,86.833 h1.52
  text "X" at 297.446,86.833 h1.52
  text "AS SHOWN" at 302.195,86.833 h1.52
  text "X" at 320.331,86.833 h1.52
  text "NC_DRILL FILES" at 323.811,86.833 h1.52
  text "PTH MIN COPPER THICKNESS:" at 280.981,82.82 h1.52
  text "X" at 315.276,82.82 h1.52
  text "1MIL" at 318.756,82.82 h1.52
  text "OTHER" at 331.38,82.82 h1.52
  text "BOARD FINISH:" at 279.081,78.782 h1.52
  text "X" at 319.95,75.911 h1.52
  text "SILKSCREEN:" at 283.024,75.784 h1.52
  text "X" at 307.123,75.784 h1.52
  text "TOP" at 310.323,75.784 h1.52
  text "BOTTOM" at 323.303,75.784 h1.52
  text "SILKSCREEN COLOR:" at 283.024,71.543 h1.52
  text "X" at 307.097,71.543 h1.52
  text "WHITE" at 310.323,71.543 h1.52
  text "OTHER" at 323.303,71.543 h1.52
  text "SOLDER RESIST COLOR:" at 283.024,67.225 h1.52
  text "X" at 297.445,63.181 h1.52
  text "GREEN" at 300.671,63.181 h1.52
  text "BLUE" at 315.683,63.181 h1.52
  text "OTHER" at 329.348,63.181 h1.52
  text "IMMERSION GOLD (ENIG)" at 306.031,58.393 h1.52
  text "ENEPIG" at 340.004,58.309 h1.52
  text "SURFACE FINISH:" at 279.081,58.284 h1.52
  text "X" at 301.282,58.284 h1.52
  text "IMM. TIN/SILVER OR EQUIV" at 287.452,54.296 h1.52
  text "OTHER" at 323.811,54.296 h1.52
  text "ARRAY/PANEL:" at 279.081,49.749 h1.52
  text "CUT AND TRIM PER MECH LAYER 1" at 306.031,49.641 h1.52
  text "N.C. ROUTE" at 306.031,45.787 h1.52
  text "X" at 323.277,45.787 h1.52
  text "V. SCORE" at 328.027,45.787 h1.52
  text "CERTIFICATION:" at 279.081,42.307 h1.52
  text "MATERIALS AND WORKMANSHIP FOR ALL PCBS" at 297.496,42.307 h1.52
  text "TO MEET OR EXCEED THE REQUIREMENTS OF:" at 297.496,39.818 h1.52
  text "X" at 288.01,36.351 h1.52
  text "ANSI IPC-A-600F CLASS ->" at 291.54,36.351 h1.52
  text "X" at 333.172,36.351 h1.52
  text "2" at 336.193,36.351 h1.52
  text "1" at 328.192,36.313 h1.52
  text "3" at 345.185,36.313 h1.52
  text "X" at 288.062,32.3 h1.52
  text "UL 94V-0" at 291.54,32.3 h1.52
  text "X" at 308.687,32.3 h1.52
  text "RoHS" at 312.165,32.3 h1.52
  text "OTHER" at 328.533,32.3 h1.52
  text "PER ORDER" at 338.618,32.3 h1.52
  text "X" at 337.947,28.829 h1.52
  text "VIA TENTING:" at 309.067,28.804 h1.52
  text "ADDITIONAL REQUIREMENTS:" at 279.081,28.718 h1.52
  text "YES" at 323.588,28.573 h1.52
  text "NO" at 333.616,28.567 h1.52
  text "MICROSECTION:" at 280.981,25.797 h1.52
  text "YES" at 303.986,25.797 h1.52
  text "IMPEDANCE CONTROL:" at 310.413,25.146 h1.52
  text "YES" at 335.001,25.121 h1.52
  text "X" at 349.174,24.943 h1.52
  text "NO" at 344.944,24.681 h1.52
  text "REQUIRED" at 325.614,21.425 h1.52
  text "BARE BOARD ELEC. TEST:" at 280.727,21.352 h1.52
  text "NONE" at 313.892,21.352 h1.52
  text "X" at 322.388,21.352 h1.52
  text "PER ORDER" at 340.651,21.352 h1.52
  text "MANUFACTURER'S UL:" at 280.727,17.364 h1.52
  text "RAIL" at 310.336,17.256 h1.52
  text "METAL" at 322.828,17.256 h1.52
  text "X" at 332.359,17.247 h1.52
  text "SILK" at 335.825,17.256 h1.52
M11 Gerber Information:
  lines w0.254: -16.18,-30.103 151.46,-30.103 ; -16.18,-24.939 151.511,-24.939 ; -16.18,-19.774 -16.18,-35.268 85.547,-35.268 151.511,-35.268 151.511,-19.774 -16.167,-19.774 -16.167,-35.268 23.851,-35.268 ; 46.431,-35.268 46.431,-19.774 ; 78.613,-24.939 78.613,-19.774 ; 99.949,-24.939 99.949,-19.774 ; 115.748,-35.433 115.748,-30.281
  text "ALL ARTWORK VIEWED FROM TOP SIDE" at -14.567,-23.131 h1.52
  text "BOARD #:" at 48.336,-23.131 h1.52
  text "TIDA-00440DB" at 60.02,-23.139 h1.52
  text "REV:" at 83.642,-23.131 h1.52
  text ".PCB_Rev" at 91.046,-23.131 h1.52
  text "SVN REV:" at 104.927,-23.131 h1.52
  text ".VersionControl_RevNumber" at 117.78,-23.131 h1.52
  text "LAYER NAME =" at -14.567,-28.283 h1.52
  text "PLOT NAME =" at -14.567,-33.511 h1.52
  text ".plot_File_Name" at 5.893,-33.511 h1.52
  text "GENERATED    :" at 48.387,-33.511 h1.52
  text ".Print_Date" at 70.472,-33.511 h1.52
  text ".Print_Time" at 88.989,-33.511 h1.52
  text "TEXAS INSTRUMENTS" at 121.107,-33.511 h1.52
M12 Stackup:
  lines w0.152: 279.222,188.709 352.146,188.709 ; 279.222,191.569 352.146,191.569 ; 277.698,170.612 ccw(c278.613,170.612) 278.613,169.697 352.755,169.697 ccw(c352.755,170.612) 353.67,170.612 353.67,194.031 ccw(c352.755,194.031) 352.755,194.945 278.613,194.945 ccw(c278.613,194.031) 277.698,194.031 277.698,170.612
  text "Layer Stack Up Detail for: TIDA-00440DB.PcbDoc" at 279.222,192.297 h1.3
  text "Layer" at 279.222,190.503 h0.66
  text "Gerber" at 304.744,190.503 h0.66
  text "Copper" at 321.484,190.503 h0.66
  text "Dielectric" at 339.302,190.503 h0.66
  text "Name" at 279.222,189.182 h0.66
  text "Document" at 304.744,189.182 h0.66
  text "Thickness" at 321.484,189.182 h0.66
  text "Material" at 339.302,189.182 h0.66
  text "Top Solder Mask" at 279.476,183.635 h0.91
  text "(.GTS)" at 304.998,183.635 h0.91
  text "Solder Resist" at 339.556,183.635 h0.91
  text "Top Layer" at 279.476,181.005 h0.91
  text "(.GTL)" at 304.998,181.005 h0.91
  text "1.4mil" at 321.738,181.005 h0.91
  text "FR-408" at 339.556,179.69 h0.91
  text "Bottom Layer" at 279.527,178.562 h0.91
  text "(.GBL)" at 304.927,178.435 h0.91
  text "1.4mil" at 321.691,178.435 h0.91
  text "Solder Resist" at 339.471,176.022 h0.91
  text "Bottom Solder Mask" at 279.527,175.895 h0.91
  text "(.GBS)" at 305.054,175.895 h0.91
M13 Component Bodies Top:
  text ".Layer_Name" at 5.893,-28.283 h1.52
M14 Component Bodies Bottom:
  text ".Layer_Name" at 5.893,-28.283 h1.52
M15 Courtyards Top:
  text ".Layer_Name" at 5.893,-28.283 h1.52
M16 Courtyards Bottom:
  text ".Layer_Name" at 5.893,-28.283 h1.52
Drill Drawing:
  text "Drill Table" at 106.477,46.761 h1.52
  text ".legend" at 106.604,15.113 h1.52
  text "DRILL TOLERANCE" at 106.502,10.897 h1.52
  text "FOR PTH +/- 3MIL" at 106.604,8.23 h1.52
  text "12mil drill:+0/-12mil" at 106.502,5.842 h1.52
  text ".Layer_Name" at 5.893,-28.283 h1.52

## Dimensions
0,0 to 75,0 on M2 Board Dimensions
0,0 to 0,52 on M2 Board Dimensions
